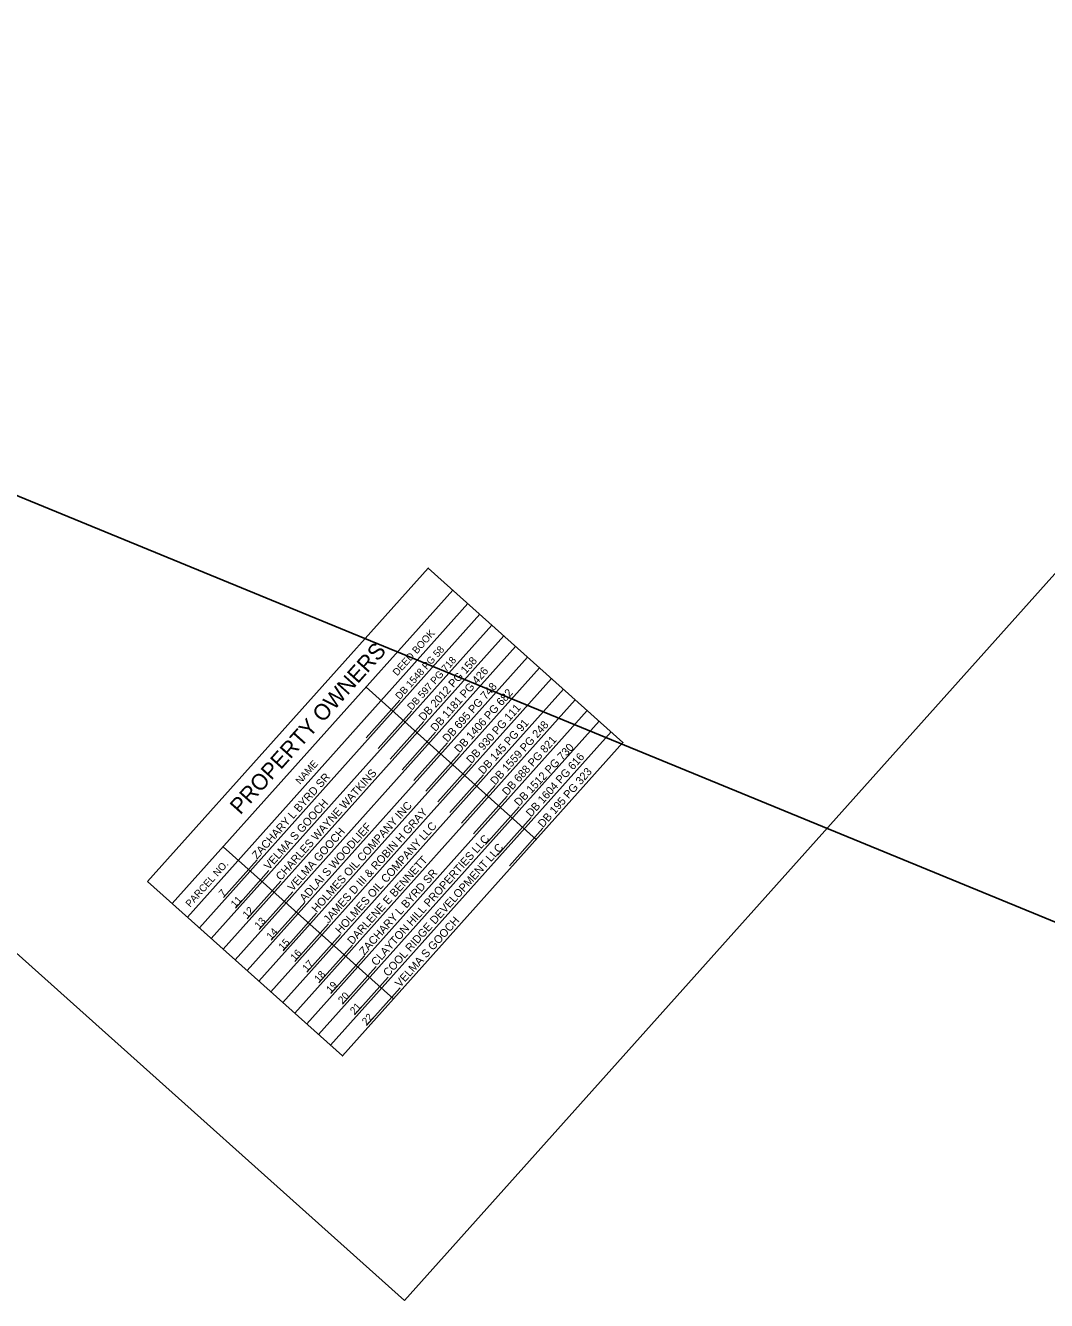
# Model space of a CAD drawing. Extents: x 2090929 to 2092919, y 862732 to 864596.
# Drawn here: x 2091567 to 2092205, y 862816 to 863612 of the extents above; entities that cross this region are included whole.
import ezdxf

# ---------------------------------------------------------------- set-up
doc = ezdxf.new("R2010")
doc.units = 0
for name, color, linetype in [('Exist Property Deed Book Text', 7, 'Continuous'), ('Exist Property Owner Text', 7, 'Continuous'), ('Scratch_Level_6', 7, 'Continuous'), ('Scratch_Level_8', 7, 'Continuous'), ('Sheet Clip Boundary CELL', 7, 'Continuous')]:
    doc.layers.add(name, color=color, linetype=linetype)

msp = doc.modelspace()

# ---------------------------------------------------------------- linework, layer by layer
at = {"layer": 'Exist Property Owner Text'}
for p, q in [((2091658.81, 863063.64), (2091834.1, 863259.48)), ((2091668.26, 863055.18), (2091843.54, 863251.03)), ((2091675.71, 863048.51), (2091850.99, 863244.36)), ((2091683.16, 863041.84), (2091858.45, 863237.69)), ((2091690.61, 863035.18), (2091865.9, 863231.02)), ((2091698.06, 863028.51), (2091873.35, 863224.35)), ((2091705.51, 863021.84), (2091880.8, 863217.68)), ((2091712.96, 863015.17), (2091888.25, 863211.01)), ((2091720.41, 863008.5), (2091895.7, 863204.35)), ((2091727.87, 863001.83), (2091903.15, 863197.68)), ((2091779.88, 863198.91), (2091886.19, 863103.76)), ((2091735.32, 862995.16), (2091910.61, 863191.01)), ((2091742.77, 862988.49), (2091918.06, 863184.34)), ((2091750.22, 862981.82), (2091925.51, 863177.67)), ((2091757.67, 862975.15), (2091932.96, 863171)), ((2091765.12, 862968.48), (2091940.41, 863164.33)), ((2091690.62, 863099.18), (2091796.94, 863004.03))]:
    msp.add_line(p, q, dxfattribs=at)
msp.add_lwpolyline([(2091643.39, 863077.44), (2091818.68, 863273.28), (2091940.41, 863164.33), (2091765.12, 862968.48)], close=True, dxfattribs=at)
at = {"layer": 'Scratch_Level_6'}
msp.add_lwpolyline([(2091346.95, 864595.83), (2092919.49, 863949.99), (2092501.6, 862932.46), (2090929.05, 863578.3)], close=True, dxfattribs=at)
at = {"layer": 'Scratch_Level_8'}
for p, q in [((2091779.99, 863167.27), (2091801.01, 863190.75)), ((2091787.45, 863160.6), (2091808.46, 863184.08)), ((2091794.9, 863153.93), (2091815.91, 863177.41)), ((2091802.35, 863147.26), (2091823.36, 863170.74)), ((2091809.8, 863140.59), (2091830.81, 863164.07)), ((2091817.25, 863133.93), (2091838.26, 863157.4)), ((2091824.7, 863127.26), (2091845.71, 863150.73)), ((2091832.15, 863120.59), (2091853.17, 863144.06)), ((2091839.61, 863113.92), (2091860.62, 863137.39)), ((2091847.06, 863107.25), (2091868.07, 863130.72)), ((2091854.51, 863100.58), (2091875.52, 863124.05)), ((2091861.96, 863093.91), (2091882.97, 863117.39)), ((2091869.41, 863087.24), (2091890.42, 863110.72)), ((2091690.74, 863067.54), (2091711.75, 863091.02)), ((2091698.19, 863060.87), (2091719.2, 863084.35)), ((2091705.64, 863054.21), (2091726.65, 863077.68)), ((2091713.09, 863047.54), (2091734.1, 863071.01)), ((2091720.54, 863040.87), (2091741.55, 863064.34)), ((2091727.99, 863034.2), (2091749, 863057.67)), ((2091735.44, 863027.53), (2091756.45, 863051)), ((2091742.9, 863020.86), (2091763.91, 863044.33)), ((2091750.35, 863014.19), (2091771.36, 863037.67)), ((2091757.8, 863007.52), (2091778.81, 863031)), ((2091765.25, 863000.85), (2091786.26, 863024.33)), ((2091772.7, 862994.18), (2091793.71, 863017.66)), ((2091780.15, 862987.51), (2091801.16, 863010.99))]:
    msp.add_line(p, q, dxfattribs=at)
at = {"layer": 'Sheet Clip Boundary CELL'}
msp.add_lwpolyline([(2091803.8, 862815.66), (2091354.16, 863218.1), (2091094.55, 863450.46), (2091157.35, 863520.81), (2091216.58, 863496.49), (2091445.4, 863779.47), (2091646.68, 863909.78), (2091657.4, 864152.65), (2091875.61, 864395.33), (2092068.41, 864222.76), (2092185.16, 864353.2), (2092693.09, 863898.58), (2092566.8, 863757.48), (2092611.19, 863717.74)], close=True, dxfattribs=at)

# ---------------------------------------------------------------- texts
at = {"layer": 'Exist Property Deed Book Text'}
for s, height, rotation, p in [('DEED BOOK', 4.5, 48.25372, (2091799.33, 863205.56)), ('PROPERTY OWNERS', 10, 48.17058, (2091701.31, 863118.68)), ('DB 1548 PG 58', 4.5, 48.17058, (2091801.01, 863190.75)), ('DB 597 PG 718', 4.5, 48.17058, (2091808.46, 863184.08)), ('DB 2012 PG 158', 5, 48.17058, (2091815.91, 863177.41)), ('DB 1181 PG 426', 5, 48.75461, (2091823.36, 863170.74)), ('DB 695 PG 748', 5, 48.17058, (2091830.81, 863164.07)), ('DB 1406 PG 682', 5, 48.17058, (2091838.26, 863157.4)), ('DB 930 PG 111', 5, 48.17058, (2091845.71, 863150.73)), ('DB 145 PG 91', 5, 48.17058, (2091853.17, 863144.06)), ('DB 1559 PG 248', 5, 48.17058, (2091860.62, 863137.39)), ('DB 688 PG 821', 5, 48.17058, (2091868.07, 863130.72)), ('DB 1512 PG 730', 5, 46.7265, (2091875.52, 863124.05)), ('DB 1604 PG 616', 5, 48.17058, (2091882.97, 863117.39)), ('NAME', 4.5, 48.25372, (2091738.66, 863137.78)), ('DB 195 PG 323', 5, 48.57276, (2091890.42, 863110.72)), ('PARCEL NO.', 4.5, 48.25372, (2091669.95, 863061)), ('7', 4.5, 48.25372, (2091690.74, 863067.54)), ('11', 4.5, 48.25372, (2091698.19, 863060.87)), ('12', 4.5, 48.25372, (2091705.64, 863054.21)), ('13', 4.5, 48.25372, (2091713.09, 863047.54)), ('14', 4.5, 48.25372, (2091720.54, 863040.87)), ('15', 4.5, 48.25372, (2091727.99, 863034.2)), ('16', 4.5, 48.25372, (2091735.44, 863027.53)), ('17', 4.5, 48.25372, (2091742.9, 863020.86)), ('18', 4.5, 48.25372, (2091750.35, 863014.19)), ('19', 4.5, 48.25372, (2091757.8, 863007.52)), ('20', 4.5, 48.25372, (2091765.25, 863000.85)), ('21', 4.5, 48.25372, (2091772.7, 862994.18)), ('22', 4.5, 48.25372, (2091780.15, 862987.51))]:
    msp.add_text(s, height=height, rotation=rotation, dxfattribs=at).set_placement(p)
at = {"layer": 'Exist Property Owner Text'}
for s, rotation, p in [('ZACHARY L BYRD SR', 48.17058, (2091711.75, 863091.02)), ('CHARLES WAYNE WATKINS', 48.17058, (2091726.65, 863077.68)), ('VELMA S GOOCH', 48.17058, (2091719.2, 863084.35)), ('HOLMES OIL COMPANY INC', 48.17058, (2091749, 863057.67)), ('JAMES D III & ROBIN H GRAY', 48.17058, (2091756.45, 863051)), ('VELMA GOOCH', 48.51382, (2091734.1, 863071.01)), ('ADLAI S WOODLIEF', 48.17058, (2091741.55, 863064.34)), ('HOLMES OIL COMPANY LLC', 48.17058, (2091763.91, 863044.33)), ('CLAYTON HILL PROPERTIES LLC', 48.22668, (2091786.26, 863024.33)), ('DARLENE E BENNETT', 48.17058, (2091771.36, 863037.67)), ('COOL RIDGE DEVELOPMENT LLC', 48.17058, (2091793.71, 863017.66)), ('ZACHARY L BYRD SR', 48.17058, (2091778.81, 863031)), ('VELMA S GOOCH', 48.17058, (2091801.16, 863010.99))]:
    msp.add_text(s, height=5, rotation=rotation, dxfattribs=at).set_placement(p)

doc.saveas('drawing.dxf')
